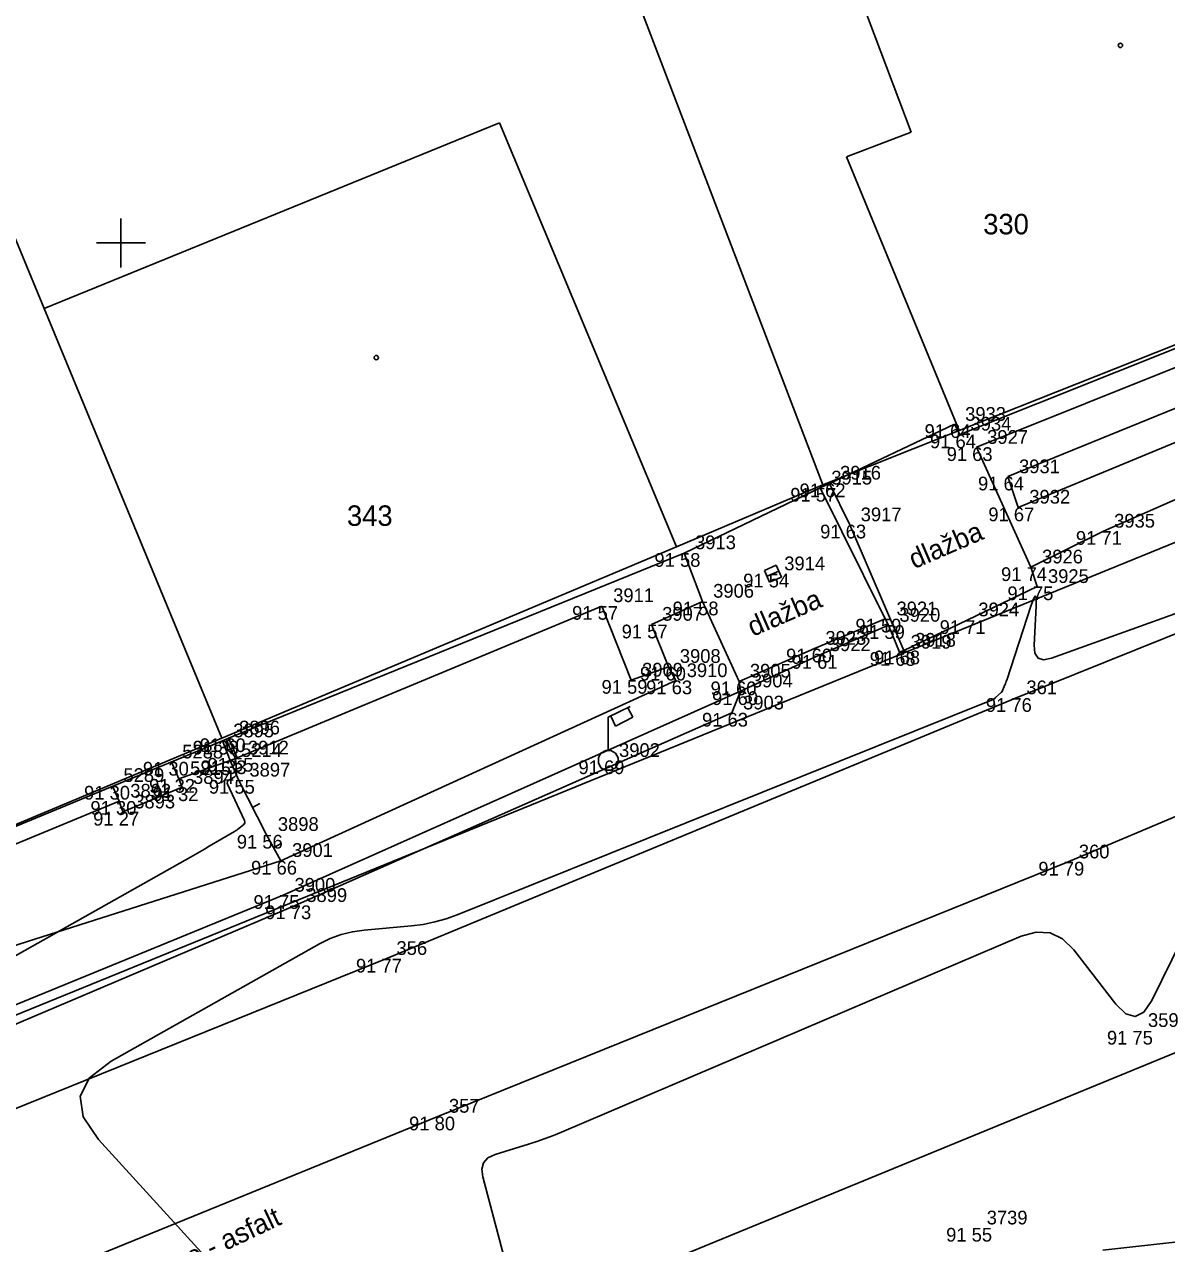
# Model space of a CAD drawing. Extents: x -711081 to -709338, y -1025122 to -1024092.
# Drawn here: x -710376.97 to -710353.67, y -1024770.42 to -1024745.54 of the extents above; entities that cross this region are included whole.
import ezdxf

# ---------------------------------------------------------------- set-up
doc = ezdxf.new("R2010")
doc.units = 0
for name, color, linetype in [('Ex_Minor Contours', 7, 'Continuous'), ('Z_body', 7, 'Continuous'), ('Z_body_cisla', 7, 'Continuous'), ('Z_body_vysky_redukovane', 7, 'Continuous'), ('Z_budova', 7, 'Continuous'), ('Z_hektometricka_sit', 7, 'Continuous'), ('Z_katastr_cisla_stavebni', 7, 'Continuous'), ('Z_katastr_hranice', 7, 'Continuous'), ('Z_katastr_hranice_katastralniho_uzemi', 7, 'Continuous'), ('Z_katastr_vnitrni_kresba', 7, 'Continuous'), ('Z_katastr_znacky_budov', 7, 'Continuous'), ('Z_komunikace', 7, 'Continuous'), ('Z_komunikace_osa', 7, 'Continuous'), ('Z_pilire', 7, 'Continuous'), ('Z_ploty', 7, 'Continuous'), ('Z_ploty_znacky', 7, 'Continuous'), ('Z_popisy', 7, 'Continuous'), ('Z_rozhranni', 7, 'Continuous'), ('Z_site_kanalizace_znaky', 7, 'Continuous'), ('Z_site_vo_znaky', 7, 'Continuous'), ('Z_vstupy', 7, 'Continuous'), ('Z_zelen_obvod', 7, 'Continuous'), ('Z_zlabek', 7, 'Continuous')]:
    doc.layers.add(name, color=color, linetype=linetype)

# ---------------------------------------------------------------- blocks, each defined once
blk = doc.blocks.new('POINT_DISPLAY')
blk.add_line((0, 0), (0, 0))
blk = doc.blocks.new('Z210')
blk.add_line((0, 0), (0, 0.17))
blk = doc.blocks.new('Z13')
for p, q in [((0, 0.88), (0.45, 1.1)), ((0.4, 1.07), (0.5, 0.88)), ((0, 0.2), (0, 0.88)), ((0.15, 0.7), (0.05, 0.9)), ((0.5, 0.88), (0.15, 0.7)), ((-0.2, 0.05), (-0.15, 0.15)), ((-0.2, -0.05), (-0.2, 0.05)), ((-0.15, 0.15), (-0.05, 0.2)), ((-0.05, 0.2), (0.05, 0.2)), ((0.05, 0.2), (0.15, 0.15)), ((0.15, 0.15), (0.2, 0.05)), ((0.2, 0.05), (0.2, -0.05)), ((-0.15, -0.15), (-0.2, -0.05)), ((-0.05, -0.2), (-0.15, -0.15)), ((0.05, -0.2), (-0.05, -0.2)), ((0.15, -0.15), (0.05, -0.2)), ((0.2, -0.05), (0.15, -0.15))]:
    blk.add_line(p, q)
blk = doc.blocks.new('Z46260')
for p, q in [((0.13, 0.13), (-0.13, 0.13)), ((-0.13, 0.13), (-0.13, -0.13)), ((0.13, 0), (-0.13, 0)), ((0.13, -0.13), (0.13, 0.13)), ((-0.13, -0.13), (0.13, -0.13))]:
    blk.add_line(p, q)

msp = doc.modelspace()

# ---------------------------------------------------------------- linework, layer by layer
at = {"layer": 'Ex_Minor Contours'}
for points in [[(-710373.221, -1024770.751), (-710375.458, -1024768.294), (-710375.769, -1024767.835), (-710375.83, -1024767.416), (-710375.64, -1024767.037), (-710375.201, -1024766.699), (-710370.948, -1024764.303), (-710370.733, -1024764.196), (-710370.51, -1024764.114), (-710370.28, -1024764.056), (-710370.042, -1024764.022), (-710369.075, -1024763.936), (-710368.835, -1024763.906), (-710368.6, -1024763.858), (-710368.368, -1024763.794), (-710368.141, -1024763.712), (-710357.243, -1024759.332), (-710357.22, -1024759.322), (-710357.198, -1024759.309), (-710357.177, -1024759.295), (-710357.158, -1024759.278), (-710357.048, -1024759.175), (-710357.045, -1024759.172), (-710357.037, -1024759.169), (-710357.035, -1024759.167), (-710357.034, -1024759.166), (-710356.97, -1024759.021), (-710356.959, -1024758.996), (-710356.949, -1024758.972), (-710356.94, -1024758.946), (-710356.931, -1024758.921), (-710356.434, -1024757.39), (-710356.381, -1024757.249), (-710356.346, -1024757.205), (-710356.329, -1024757.258), (-710356.331, -1024757.41), (-710356.372, -1024758.209), (-710356.357, -1024758.375), (-710356.293, -1024758.474), (-710356.179, -1024758.507), (-710356.016, -1024758.473), (-710346.334, -1024754.992)], [(-710372.854, -1024760.129), (-710372.81, -1024760.24), (-710372.802, -1024760.258), (-710372.794, -1024760.276), (-710372.785, -1024760.294), (-710372.776, -1024760.312), (-710372.695, -1024760.46), (-710372.68, -1024760.491), (-710372.669, -1024760.523), (-710372.661, -1024760.557), (-710372.657, -1024760.591), (-710372.643, -1024760.808), (-710372.644, -1024760.837), (-710372.653, -1024760.862), (-710372.669, -1024760.883), (-710372.691, -1024760.9), (-710372.797, -1024760.962), (-710372.819, -1024760.979), (-710372.83, -1024760.999), (-710372.832, -1024761.022), (-710372.824, -1024761.048), (-710372.484, -1024761.786), (-710372.476, -1024761.811), (-710372.477, -1024761.834), (-710372.486, -1024761.855), (-710372.504, -1024761.874), (-710372.592, -1024761.946), (-710372.615, -1024761.964), (-710372.638, -1024761.981), (-710372.661, -1024761.997), (-710372.686, -1024762.012), (-710373.204, -1024762.314), (-710373.299, -1024762.369), (-710373.394, -1024762.424), (-710373.489, -1024762.478), (-710373.584, -1024762.532), (-710381.16, -1024766.802)], [(-710353.359, -1024764.215), (-710353.973, -1024765.458), (-710354.134, -1024765.696), (-710354.31, -1024765.788), (-710354.5, -1024765.733), (-710354.705, -1024765.532), (-710355.565, -1024764.426), (-710355.793, -1024764.202), (-710356.047, -1024764.081), (-710356.328, -1024764.063), (-710356.636, -1024764.149), (-710366.014, -1024768.144), (-710366.18, -1024768.212), (-710366.347, -1024768.276), (-710366.516, -1024768.335), (-710366.686, -1024768.391), (-710367.37, -1024768.605), (-710367.514, -1024768.673), (-710367.604, -1024768.771), (-710367.639, -1024768.9), (-710367.621, -1024769.058), (-710367.186, -1024770.705)], [(-710354.968, -1024770.555), (-710353.378, -1024770.376)]]:
    msp.add_lwpolyline(points, dxfattribs=at)
at = {"layer": 'Z_budova'}
for p, q in [((-710357.89, -1024753.91), (-710348.39, -1024750.11)), ((-710358, -1024753.7), (-710357.89, -1024753.91)), ((-710372.81, -1024760.11), (-710363.51, -1024756.33)), ((-710384.1, -1024764.78), (-710372.93, -1024760.16)), ((-710372.93, -1024760.16), (-710372.81, -1024760.11))]:
    msp.add_line(p, q, dxfattribs=at)
at = {"layer": 'Z_hektometricka_sit'}
for p, q in [((-710375, -1024749.5), (-710375, -1024750.5)), ((-710375.5, -1024750), (-710374.5, -1024750))]:
    msp.add_line(p, q, dxfattribs=at)
at = {"layer": 'Z_katastr_hranice'}
for p, q in [((-710365.67, -1024741.88), (-710360.68, -1024754.94)), ((-710378.9, -1024745.7), (-710376.57, -1024751.34)), ((-710357.9, -1024753.83), (-710348.48, -1024750.08)), ((-710376.57, -1024751.34), (-710372.94, -1024760.11)), ((-710360.68, -1024754.94), (-710357.9, -1024753.83)), ((-710363.67, -1024756.2), (-710360.68, -1024754.94)), ((-710372.94, -1024760.11), (-710363.67, -1024756.2)), ((-710445.08, -1024804.13), (-710335.33, -1024759.07)), ((-710388.12, -1024766.45), (-710372.94, -1024760.11))]:
    msp.add_line(p, q, dxfattribs=at)
at = {"layer": 'Z_katastr_hranice_katastralniho_uzemi'}
msp.add_line((-710277.4, -1024725.07), (-710392.31, -1024771.94), dxfattribs=at)
msp.add_line((-710277.4, -1024725.07), (-710392.31, -1024771.94), dxfattribs=at)
at = {"layer": 'Z_katastr_vnitrni_kresba'}
for p, q in [((-710359.89, -1024745.07), (-710358.88, -1024747.74)), ((-710376.57, -1024751.34), (-710367.28, -1024747.55)), ((-710367.28, -1024747.55), (-710363.67, -1024756.2)), ((-710358.88, -1024747.74), (-710360.2, -1024748.24)), ((-710360.2, -1024748.24), (-710357.9, -1024753.83))]:
    msp.add_line(p, q, dxfattribs=at)
at = {"layer": 'Z_katastr_znacky_budov'}
for centre in [(-710354.612, -1024745.97), (-710369.792, -1024752.34)]:
    msp.add_circle(centre, 0.0437, dxfattribs=at)
at = {"layer": 'Z_komunikace'}
for p, q in [((-710356.75, -1024759.29), (-710343.77, -1024754.07)), ((-710369.6, -1024764.61), (-710356.75, -1024759.29)), ((-710383.06, -1024770.06), (-710369.6, -1024764.61))]:
    msp.add_line(p, q, dxfattribs=at)
at = {"layer": 'Z_komunikace_osa'}
for p, q in [((-710355.68, -1024762.63), (-710342.58, -1024757.09)), ((-710368.54, -1024767.83), (-710355.68, -1024762.63)), ((-710382.41, -1024773.48), (-710368.54, -1024767.83))]:
    msp.add_line(p, q, dxfattribs=at)
at = {"layer": 'Z_pilire'}
for p, q in [((-710373.82, -1024760.94), (-710373.97, -1024760.59)), ((-710375.04, -1024761.39), (-710375.17, -1024761.08)), ((-710374.96, -1024761.61), (-710373.75, -1024761.11)), ((-710373.75, -1024761.11), (-710373.82, -1024760.94)), ((-710374.96, -1024761.61), (-710375.04, -1024761.39))]:
    msp.add_line(p, q, dxfattribs=at)
at = {"layer": 'Z_ploty'}
for p, q in [((-710360.74, -1024755), (-710360.55, -1024754.91)), ((-710372.77, -1024760.56), (-710372.93, -1024760.16)), ((-710372.6, -1024760.96), (-710372.77, -1024760.56)), ((-710372.6, -1024760.96), (-710372.03, -1024762.08)), ((-710372.03, -1024762.08), (-710371.74, -1024762.61))]:
    msp.add_line(p, q, dxfattribs=at)
at = {"layer": 'Z_rozhranni'}
for p, q in [((-710357.55, -1024754.17), (-710348.3, -1024750.46)), ((-710354.96, -1024755.88), (-710347.76, -1024752.73)), ((-710356.44, -1024756.62), (-710357.55, -1024754.17)), ((-710360.13, -1024755.75), (-710360.55, -1024754.91)), ((-710359.41, -1024757.67), (-710360.74, -1024755)), ((-710360.13, -1024755.75), (-710359.03, -1024758.32)), ((-710354.96, -1024755.88), (-710356.44, -1024756.62)), ((-710363.51, -1024756.33), (-710363.14, -1024757.32)), ((-710356.31, -1024757.01), (-710356.44, -1024756.62)), ((-710357.74, -1024757.7), (-710356.31, -1024757.01)), ((-710365.19, -1024757.41), (-710372.63, -1024760.51)), ((-710364.59, -1024758.92), (-710365.19, -1024757.41)), ((-710363.14, -1024757.32), (-710364.18, -1024757.79)), ((-710362.39, -1024758.95), (-710363.14, -1024757.32)), ((-710359.34, -1024757.8), (-710359.41, -1024757.67)), ((-710364.18, -1024757.79), (-710363.83, -1024758.65)), ((-710359.12, -1024758.35), (-710359.34, -1024757.8)), ((-710359.03, -1024758.32), (-710357.74, -1024757.7)), ((-710359.03, -1024758.32), (-710359.12, -1024758.35)), ((-710363.83, -1024758.65), (-710364.59, -1024758.92)), ((-710362.54, -1024759.59), (-710362.36, -1024759.15)), ((-710362.36, -1024759.15), (-710362.39, -1024758.95)), ((-710371.45, -1024763.52), (-710362.54, -1024759.59)), ((-710372.81, -1024760.11), (-710372.63, -1024760.51)), ((-710373.82, -1024760.94), (-710372.77, -1024760.56)), ((-710372.77, -1024760.56), (-710372.63, -1024760.51)), ((-710383.96, -1024765.09), (-710375.04, -1024761.39)), ((-710383.54, -1024768.66), (-710371.45, -1024763.52))]:
    msp.add_line(p, q, dxfattribs=at)
at = {"layer": 'Z_vstupy'}
for p, q in [((-710360.55, -1024754.91), (-710358, -1024753.7)), ((-710363.51, -1024756.33), (-710360.74, -1024755))]:
    msp.add_line(p, q, dxfattribs=at)
at = {"layer": 'Z_zelen_obvod'}
for p, q in [((-710347.82, -1024751.05), (-710356.91, -1024754.77)), ((-710356.7, -1024755.4), (-710347.52, -1024751.59)), ((-710356.91, -1024754.77), (-710356.7, -1024755.4)), ((-710363.68, -1024758.93), (-710363.83, -1024758.65)), ((-710371.74, -1024762.61), (-710363.68, -1024758.93)), ((-710371.69, -1024763.31), (-710362.36, -1024759.15)), ((-710384.34, -1024766.62), (-710371.74, -1024762.61)), ((-710383.69, -1024768.22), (-710371.69, -1024763.31))]:
    msp.add_line(p, q, dxfattribs=at)
at = {"layer": 'Z_zlabek'}
for p, q in [((-710360.85, -1024758.28), (-710359.41, -1024757.67)), ((-710359.34, -1024757.8), (-710360.76, -1024758.41)), ((-710362.39, -1024758.95), (-710360.85, -1024758.28)), ((-710360.76, -1024758.41), (-710362.36, -1024759.15))]:
    msp.add_line(p, q, dxfattribs=at)

# ---------------------------------------------------------------- block references
at = {"layer": 'Z_body'}
for p in [(-710358, -1024753.7), (-710357.89, -1024753.91), (-710357.55, -1024754.17), (-710360.55, -1024754.91), (-710356.91, -1024754.77), (-710360.74, -1024755), (-710356.7, -1024755.4), (-710360.13, -1024755.75), (-710354.96, -1024755.88), (-710363.51, -1024756.33), (-710356.44, -1024756.62), (-710361.7, -1024756.75), (-710356.31, -1024757.01), (-710365.19, -1024757.41), (-710363.14, -1024757.32), (-710359.41, -1024757.67), (-710364.18, -1024757.79), (-710359.34, -1024757.8), (-710357.74, -1024757.7), (-710360.85, -1024758.28), (-710360.76, -1024758.41), (-710359.12, -1024758.35), (-710359.03, -1024758.32), (-710363.83, -1024758.65), (-710364.59, -1024758.92), (-710363.68, -1024758.93), (-710362.39, -1024758.95), (-710362.36, -1024759.15), (-710356.75, -1024759.29), (-710362.54, -1024759.59), (-710372.93, -1024760.16), (-710372.81, -1024760.11), (-710373.97, -1024760.59), (-710372.77, -1024760.56), (-710372.63, -1024760.51), (-710365.06, -1024760.56), (-710375.17, -1024761.08), (-710373.82, -1024760.94), (-710373.75, -1024761.11), (-710372.6, -1024760.96), (-710375.04, -1024761.39), (-710374.96, -1024761.61), (-710372.03, -1024762.08), (-710371.74, -1024762.61), (-710355.68, -1024762.63), (-710371.69, -1024763.31), (-710371.45, -1024763.52), (-710369.6, -1024764.61), (-710354.28, -1024766.08), (-710368.54, -1024767.83), (-710357.56, -1024770.1)]:
    msp.add_blockref('POINT_DISPLAY', p, dxfattribs=at)
at = {"layer": 'Z_ploty_znacky'}
for p, rotation in [((-710372.85, -1024760.36), -68.19999999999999), ((-710372.69, -1024760.76), -67.00000000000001), ((-710372.32, -1024761.52), -63.000000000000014), ((-710372.32, -1024761.52), -63.000000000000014), ((-710372.32, -1024761.52), -63.000000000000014), ((-710371.88, -1024762.34), -61.30000000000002)]:
    msp.add_blockref('Z210', p, dxfattribs=dict(at, rotation=rotation))
at = {"layer": 'Z_site_kanalizace_znaky', "rotation": 23.399999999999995}
msp.add_blockref('Z46260', (-710361.7, -1024756.75), dxfattribs=at)
at = {"layer": 'Z_site_vo_znaky'}
msp.add_blockref('Z13', (-710365.06, -1024760.56), dxfattribs=at)

# ---------------------------------------------------------------- texts
at = {"layer": 'Z_body_cisla'}
for s, p in [('3933', (-710357.78, -1024753.63)), ('3934', (-710357.67, -1024753.83)), ('3927', (-710357.33, -1024754.1)), ('3931', (-710356.68, -1024754.7)), ('3915', (-710360.51, -1024754.93)), ('3916', (-710360.33, -1024754.83)), ('3932', (-710356.47, -1024755.32)), ('3917', (-710359.91, -1024755.68)), ('3935', (-710354.74, -1024755.81)), ('3913', (-710363.29, -1024756.25)), ('3914', (-710361.47, -1024756.68)), ('3926', (-710356.21, -1024756.54)), ('3925', (-710356.09, -1024756.94)), ('3911', (-710364.96, -1024757.33)), ('3906', (-710362.92, -1024757.24)), ('3907', (-710363.96, -1024757.71)), ('3921', (-710359.18, -1024757.6)), ('3924', (-710357.51, -1024757.62)), ('3920', (-710359.12, -1024757.73)), ('3923', (-710360.63, -1024758.2)), ('3922', (-710360.54, -1024758.33)), ('3919', (-710358.89, -1024758.28)), ('3918', (-710358.8, -1024758.24)), ('3908', (-710363.6, -1024758.57)), ('3909', (-710364.37, -1024758.85)), ('3910', (-710363.46, -1024758.86)), ('3905', (-710362.17, -1024758.87)), ('3904', (-710362.13, -1024759.07)), ('361', (-710356.53, -1024759.21)), ('3903', (-710362.31, -1024759.52)), ('3895', (-710372.71, -1024760.09)), ('3896', (-710372.59, -1024760.03)), ('3912', (-710372.41, -1024760.44)), ('5288', (-710373.75, -1024760.52)), ('5214', (-710372.55, -1024760.49)), ('3902', (-710364.84, -1024760.49)), ('5215', (-710373.59, -1024760.86)), ('3897', (-710372.38, -1024760.89)), ('5289', (-710374.95, -1024761)), ('3894', (-710373.53, -1024761.04)), ('3892', (-710374.81, -1024761.32)), ('3893', (-710374.73, -1024761.54)), ('3898', (-710371.8, -1024762)), ('3901', (-710371.51, -1024762.53)), ('360', (-710355.46, -1024762.56)), ('3900', (-710371.46, -1024763.24)), ('3899', (-710371.22, -1024763.45)), ('356', (-710369.38, -1024764.53)), ('359', (-710354.05, -1024766)), ('357', (-710368.31, -1024767.75)), ('3739', (-710357.34, -1024770.03))]:
    msp.add_text(s, height=0.28, dxfattribs=at).set_placement(p)
at = {"layer": 'Z_body_vysky_redukovane'}
for s, p in [('91 64', (-710358.607, -1024753.98)), ('91 64', (-710358.497, -1024754.19)), ('91 63', (-710358.157, -1024754.45)), ('91 62', (-710361.157, -1024755.19)), ('91 64', (-710357.517, -1024755.05)), ('91 57', (-710361.347, -1024755.28)), ('91 67', (-710357.307, -1024755.68)), ('91 63', (-710360.737, -1024756.03)), ('91 71', (-710355.52, -1024756.16)), ('91 58', (-710364.117, -1024756.61)), ('91 74', (-710357.047, -1024756.9)), ('91 54', (-710362.307, -1024757.03)), ('91 75', (-710356.917, -1024757.29)), ('91 57', (-710365.797, -1024757.69)), ('91 58', (-710363.747, -1024757.6)), ('91 59', (-710360.017, -1024757.95)), ('91 57', (-710364.787, -1024758.07)), ('91 59', (-710359.947, -1024758.08)), ('91 71', (-710358.3, -1024757.98)), ('91 60', (-710361.433, -1024758.56)), ('91 61', (-710361.32, -1024758.69)), ('91 68', (-710359.727, -1024758.63)), ('91 68', (-710359.637, -1024758.6)), ('91 60', (-710364.413, -1024758.93)), ('91 59', (-710365.197, -1024759.2)), ('91 63', (-710364.287, -1024759.21)), ('91 60', (-710362.973, -1024759.23)), ('91 60', (-710362.943, -1024759.43)), ('91 76', (-710357.357, -1024759.57)), ('91 63', (-710363.147, -1024759.87)), ('91 33', (-710373.537, -1024760.44)), ('91 60', (-710373.393, -1024760.39)), ('91 30', (-710374.553, -1024760.87)), ('91 33', (-710373.377, -1024760.84)), ('91 55', (-710373.237, -1024760.79)), ('91 69', (-710365.667, -1024760.84)), ('91 30', (-710375.753, -1024761.36)), ('91 32', (-710374.427, -1024761.22)), ('91 32', (-710374.357, -1024761.39)), ('91 55', (-710373.207, -1024761.24)), ('91 30', (-710375.623, -1024761.67)), ('91 27', (-710375.567, -1024761.89)), ('91 56', (-710372.637, -1024762.36)), ('91 66', (-710372.347, -1024762.89)), ('91 79', (-710356.287, -1024762.91)), ('91 75', (-710372.297, -1024763.59)), ('91 73', (-710372.057, -1024763.8)), ('91 77', (-710370.207, -1024764.89)), ('91 75', (-710354.887, -1024766.36)), ('91 80', (-710369.123, -1024768.11)), ('91 55', (-710358.167, -1024770.38))]:
    msp.add_text(s, height=0.28, dxfattribs=at).set_placement(p)
at = {"layer": 'Z_katastr_cisla_stavebni'}
for s, p in [('330', (-710357.411, -1024749.825)), ('343', (-710370.391, -1024755.774))]:
    msp.add_text(s, height=0.4175, dxfattribs=at).set_placement(p)
at = {"layer": 'Z_popisy'}
for s, rotation, p in [('dlažba', 23.4, (-710358.82, -1024756.66)), ('dlažba', 23.4, (-710362.11, -1024758.04)), ('Komunikace - asfalt', 25.2, (-710375.95, -1024772.02))]:
    msp.add_text(s, height=0.4, rotation=rotation, dxfattribs=at).set_placement(p)

doc.saveas('drawing.dxf')
